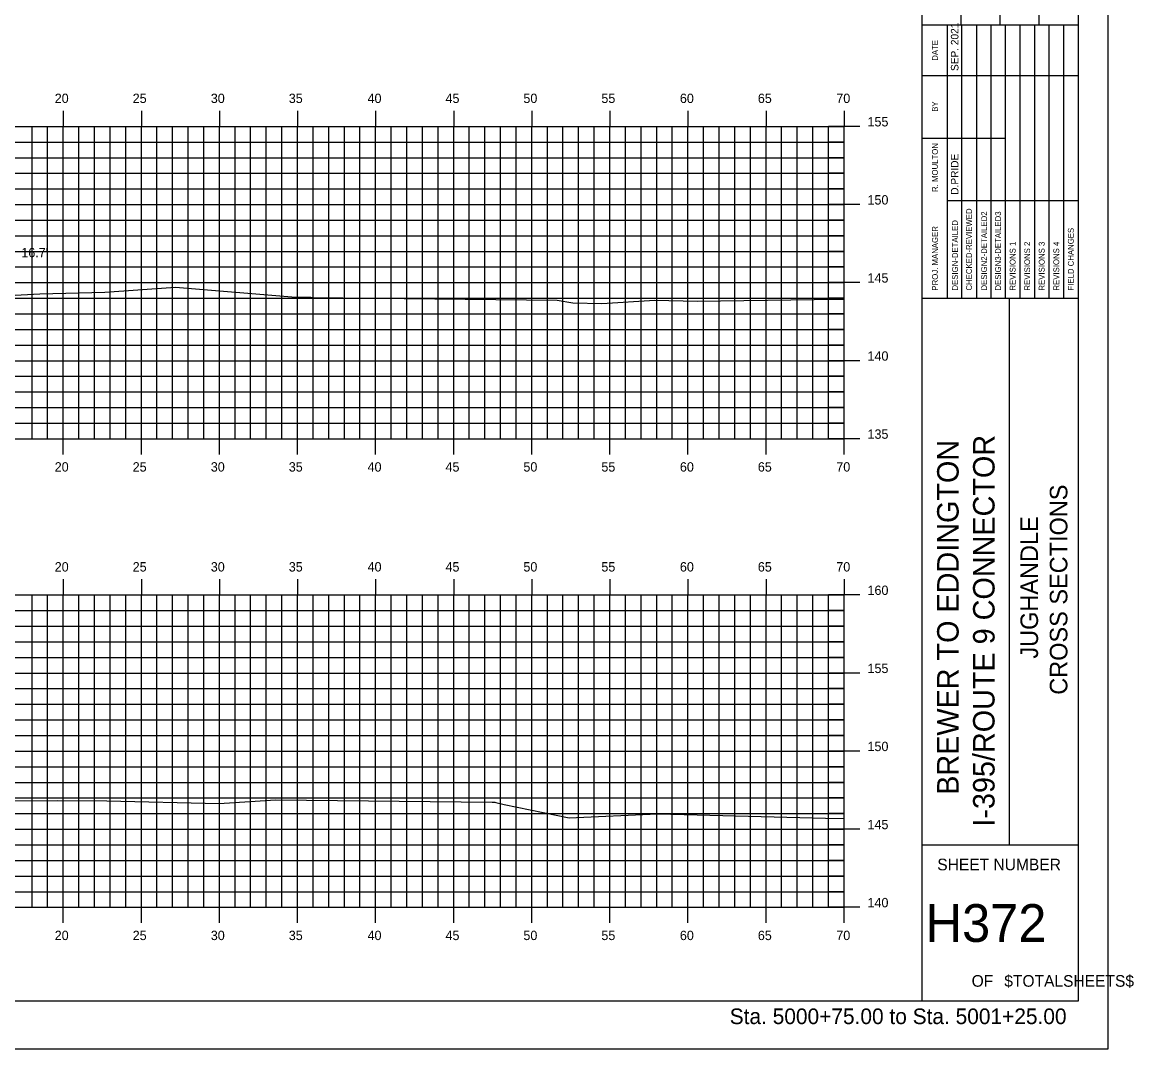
# Model space of a CAD drawing. Extents: x 850973 to 851145, y 365876 to 365986.
# Drawn here: x 851073.8 to 851144.9, y 365875.8 to 365941.5 of the extents above; entities that cross this region are included whole.
import ezdxf

# ---------------------------------------------------------------- set-up
doc = ezdxf.new("R2010")
doc.units = 0
for name, color, linetype in [('BORDER', 7, 'Continuous'), ('D_Text_Standard', 7, 'Continuous'), ('H_V ANNOTATION', 7, 'Continuous'), ('MAJOR', 7, 'Continuous'), ('MINOR', 7, 'Continuous'), ('PLOT BOUNDARY', 7, 'Continuous'), ('S_Roadway_Centerline', 7, 'Continuous')]:
    doc.layers.add(name, color=color, linetype=linetype)

msp = doc.modelspace()

# ---------------------------------------------------------------- linework, layer by layer
at = {"layer": 'BORDER'}
for p, q in [((851131.386, 365878.833), (851131.386, 365983.833)), ((851133.886, 365941.336), (851133.886, 365949.984)), ((851136.386, 365941.336), (851136.386, 365949.984)), ((851138.886, 365941.336), (851138.886, 365949.984)), ((851131.386, 365941.336), (851141.386, 365941.336)), ((851131.386, 365923.836), (851141.386, 365923.836)), ((851136.977, 365888.836), (851136.977, 365923.836)), ((851131.386, 365888.836), (851141.386, 365888.836))]:
    msp.add_line(p, q, dxfattribs=at)
msp.add_lwpolyline([(850981.386, 365878.833), (851141.386, 365878.833), (851141.386, 365983.833), (850981.386, 365983.833)], close=True, dxfattribs=at)
for points in [[(851133, 365938.086), (851133, 365941.336)], [(851133.933, 365923.839), (851133.933, 365941.336)], [(851134.865, 365941.336), (851134.865, 365923.839)], [(851135.796, 365923.839), (851135.796, 365941.336)], [(851136.728, 365923.839), (851136.728, 365941.336)], [(851137.66, 365923.839), (851137.66, 365941.336)], [(851138.591, 365923.839), (851138.591, 365941.336)], [(851139.523, 365923.839), (851139.523, 365941.336)], [(851140.455, 365923.839), (851140.455, 365941.336)], [(851133.001, 365923.839), (851133.001, 365940.63)], [(851131.386, 365938.086), (851141.386, 365938.086)], [(851131.386, 365934.086), (851133.001, 365934.086)], [(851133, 365934.086), (851136.727, 365934.086)], [(851133, 365930.086), (851141.386, 365930.086)]]:
    msp.add_lwpolyline(points, dxfattribs=at)
at = {"layer": 'MAJOR'}
for p, q in [((851076.385, 365935.835), (851076.385, 365934.833)), ((851081.385, 365935.835), (851081.385, 365934.833)), ((851086.385, 365935.835), (851086.385, 365934.833)), ((851091.385, 365935.835), (851091.385, 365934.833)), ((851096.385, 365935.835), (851096.385, 365934.833)), ((851101.385, 365935.835), (851101.385, 365934.833)), ((851106.385, 365935.835), (851106.385, 365934.833)), ((851111.385, 365935.835), (851111.385, 365934.833)), ((851116.385, 365935.835), (851116.385, 365934.833)), ((851121.385, 365935.835), (851121.385, 365934.833)), ((851126.385, 365935.835), (851126.385, 365934.833)), ((850986.385, 365934.833), (851126.385, 365934.833)), ((850986.385, 365934.833), (851126.385, 365934.833)), ((851076.385, 365914.833), (851076.385, 365934.833)), ((851081.385, 365914.833), (851081.385, 365934.833)), ((851086.385, 365914.833), (851086.385, 365934.833)), ((851091.385, 365914.833), (851091.385, 365934.833)), ((851096.385, 365914.833), (851096.385, 365934.833)), ((851101.385, 365914.833), (851101.385, 365934.833)), ((851106.385, 365914.833), (851106.385, 365934.833)), ((851111.385, 365914.833), (851111.385, 365934.833)), ((851116.385, 365914.833), (851116.385, 365934.833)), ((851121.385, 365914.833), (851121.385, 365934.833)), ((851127.387, 365934.833), (851125.383, 365934.833)), ((851126.385, 365914.833), (851126.385, 365934.833)), ((851126.385, 365914.833), (851126.385, 365934.833)), ((850986.385, 365929.833), (851126.385, 365929.833)), ((851127.387, 365929.833), (851125.383, 365929.833)), ((850986.385, 365924.833), (851126.385, 365924.833)), ((851127.387, 365924.833), (851125.383, 365924.833)), ((850986.385, 365919.833), (851126.385, 365919.833)), ((851127.387, 365919.833), (851125.383, 365919.833)), ((850986.385, 365914.833), (851126.385, 365914.833)), ((850986.385, 365914.833), (851126.385, 365914.833)), ((851076.385, 365913.831), (851076.385, 365914.833)), ((851081.385, 365913.831), (851081.385, 365914.833)), ((851086.385, 365913.831), (851086.385, 365914.833)), ((851091.385, 365913.831), (851091.385, 365914.833)), ((851096.385, 365913.831), (851096.385, 365914.833)), ((851101.385, 365913.831), (851101.385, 365914.833)), ((851106.385, 365913.831), (851106.385, 365914.833)), ((851111.385, 365913.831), (851111.385, 365914.833)), ((851116.385, 365913.831), (851116.385, 365914.833)), ((851121.385, 365913.831), (851121.385, 365914.833)), ((851127.387, 365914.833), (851125.383, 365914.833)), ((851126.385, 365913.831), (851126.385, 365914.833)), ((851076.385, 365905.835), (851076.385, 365904.833)), ((851081.385, 365905.835), (851081.385, 365904.833)), ((851086.385, 365905.835), (851086.385, 365904.833)), ((851091.385, 365905.835), (851091.385, 365904.833)), ((851096.385, 365905.835), (851096.385, 365904.833)), ((851101.385, 365905.835), (851101.385, 365904.833)), ((851106.385, 365905.835), (851106.385, 365904.833)), ((851111.385, 365905.835), (851111.385, 365904.833)), ((851116.385, 365905.835), (851116.385, 365904.833)), ((851121.385, 365905.835), (851121.385, 365904.833)), ((851126.385, 365905.835), (851126.385, 365904.833)), ((850986.385, 365904.833), (851126.385, 365904.833)), ((850986.385, 365904.833), (851126.385, 365904.833)), ((851076.385, 365884.833), (851076.385, 365904.833)), ((851081.385, 365884.833), (851081.385, 365904.833)), ((851086.385, 365884.833), (851086.385, 365904.833)), ((851091.385, 365884.833), (851091.385, 365904.833)), ((851096.385, 365884.833), (851096.385, 365904.833)), ((851101.385, 365884.833), (851101.385, 365904.833)), ((851106.385, 365884.833), (851106.385, 365904.833)), ((851111.385, 365884.833), (851111.385, 365904.833)), ((851116.385, 365884.833), (851116.385, 365904.833)), ((851121.385, 365884.833), (851121.385, 365904.833)), ((851127.387, 365904.833), (851125.383, 365904.833)), ((851126.385, 365884.833), (851126.385, 365904.833)), ((851126.385, 365884.833), (851126.385, 365904.833)), ((850986.385, 365899.833), (851126.385, 365899.833)), ((851127.387, 365899.833), (851125.383, 365899.833)), ((850986.385, 365894.833), (851126.385, 365894.833)), ((851127.387, 365894.833), (851125.383, 365894.833)), ((850986.385, 365889.833), (851126.385, 365889.833)), ((851127.387, 365889.833), (851125.383, 365889.833)), ((850986.385, 365884.833), (851126.385, 365884.833)), ((850986.385, 365884.833), (851126.385, 365884.833)), ((851076.385, 365883.831), (851076.385, 365884.833)), ((851081.385, 365883.831), (851081.385, 365884.833)), ((851086.385, 365883.831), (851086.385, 365884.833)), ((851091.385, 365883.831), (851091.385, 365884.833)), ((851096.385, 365883.831), (851096.385, 365884.833)), ((851101.385, 365883.831), (851101.385, 365884.833)), ((851106.385, 365883.831), (851106.385, 365884.833)), ((851111.385, 365883.831), (851111.385, 365884.833)), ((851116.385, 365883.831), (851116.385, 365884.833)), ((851121.385, 365883.831), (851121.385, 365884.833)), ((851127.387, 365884.833), (851125.383, 365884.833)), ((851126.385, 365883.831), (851126.385, 365884.833))]:
    msp.add_line(p, q, dxfattribs=at)
at = {"layer": 'MINOR'}
for p, q in [((851074.385, 365914.833), (851074.385, 365934.833)), ((851075.385, 365914.833), (851075.385, 365934.833)), ((851077.385, 365914.833), (851077.385, 365934.833)), ((851078.385, 365914.833), (851078.385, 365934.833)), ((851079.385, 365914.833), (851079.385, 365934.833)), ((851080.385, 365914.833), (851080.385, 365934.833)), ((851082.385, 365914.833), (851082.385, 365934.833)), ((851083.385, 365914.833), (851083.385, 365934.833)), ((851084.385, 365914.833), (851084.385, 365934.833)), ((851085.385, 365914.833), (851085.385, 365934.833)), ((851087.385, 365914.833), (851087.385, 365934.833)), ((851088.385, 365914.833), (851088.385, 365934.833)), ((851089.385, 365914.833), (851089.385, 365934.833)), ((851090.385, 365914.833), (851090.385, 365934.833)), ((851092.385, 365914.833), (851092.385, 365934.833)), ((851093.385, 365914.833), (851093.385, 365934.833)), ((851094.385, 365914.833), (851094.385, 365934.833)), ((851095.385, 365914.833), (851095.385, 365934.833)), ((851097.385, 365914.833), (851097.385, 365934.833)), ((851098.385, 365914.833), (851098.385, 365934.833)), ((851099.385, 365914.833), (851099.385, 365934.833)), ((851100.385, 365914.833), (851100.385, 365934.833)), ((851102.385, 365914.833), (851102.385, 365934.833)), ((851103.385, 365914.833), (851103.385, 365934.833)), ((851104.385, 365914.833), (851104.385, 365934.833)), ((851105.385, 365914.833), (851105.385, 365934.833)), ((851107.385, 365914.833), (851107.385, 365934.833)), ((851108.385, 365914.833), (851108.385, 365934.833)), ((851109.385, 365914.833), (851109.385, 365934.833)), ((851110.385, 365914.833), (851110.385, 365934.833)), ((851112.385, 365914.833), (851112.385, 365934.833)), ((851113.385, 365914.833), (851113.385, 365934.833)), ((851114.385, 365914.833), (851114.385, 365934.833)), ((851115.385, 365914.833), (851115.385, 365934.833)), ((851117.385, 365914.833), (851117.385, 365934.833)), ((851118.385, 365914.833), (851118.385, 365934.833)), ((851119.385, 365914.833), (851119.385, 365934.833)), ((851120.385, 365914.833), (851120.385, 365934.833)), ((851122.385, 365914.833), (851122.385, 365934.833)), ((851123.385, 365914.833), (851123.385, 365934.833)), ((851124.385, 365914.833), (851124.385, 365934.833)), ((851125.385, 365914.833), (851125.385, 365934.833)), ((850986.385, 365933.833), (851126.385, 365933.833)), ((851126.385, 365933.833), (851125.383, 365933.833)), ((850986.385, 365932.833), (851126.385, 365932.833)), ((851126.385, 365932.833), (851125.383, 365932.833)), ((850986.385, 365931.833), (851126.385, 365931.833)), ((851126.385, 365931.833), (851125.383, 365931.833)), ((850986.385, 365930.833), (851126.385, 365930.833)), ((851126.385, 365930.833), (851125.383, 365930.833)), ((850986.385, 365928.833), (851126.385, 365928.833)), ((851126.385, 365928.833), (851125.383, 365928.833)), ((850986.385, 365927.833), (851126.385, 365927.833)), ((851126.385, 365927.833), (851125.383, 365927.833)), ((850986.385, 365926.833), (851126.385, 365926.833)), ((851126.385, 365926.833), (851125.383, 365926.833)), ((850986.385, 365925.833), (851126.385, 365925.833)), ((851126.385, 365925.833), (851125.383, 365925.833)), ((850986.385, 365923.833), (851126.385, 365923.833)), ((851126.385, 365923.833), (851125.383, 365923.833)), ((850986.385, 365922.833), (851126.385, 365922.833)), ((851126.385, 365922.833), (851125.383, 365922.833)), ((850986.385, 365921.833), (851126.385, 365921.833)), ((851126.385, 365921.833), (851125.383, 365921.833)), ((850986.385, 365920.833), (851126.385, 365920.833)), ((851126.385, 365920.833), (851125.383, 365920.833)), ((850986.385, 365918.833), (851126.385, 365918.833)), ((851126.385, 365918.833), (851125.383, 365918.833)), ((850986.385, 365917.833), (851126.385, 365917.833)), ((851126.385, 365917.833), (851125.383, 365917.833)), ((850986.385, 365916.833), (851126.385, 365916.833)), ((851126.385, 365916.833), (851125.383, 365916.833)), ((850986.385, 365915.833), (851126.385, 365915.833)), ((851126.385, 365915.833), (851125.383, 365915.833)), ((851074.385, 365884.833), (851074.385, 365904.833)), ((851075.385, 365884.833), (851075.385, 365904.833)), ((851077.385, 365884.833), (851077.385, 365904.833)), ((851078.385, 365884.833), (851078.385, 365904.833)), ((851079.385, 365884.833), (851079.385, 365904.833)), ((851080.385, 365884.833), (851080.385, 365904.833)), ((851082.385, 365884.833), (851082.385, 365904.833)), ((851083.385, 365884.833), (851083.385, 365904.833)), ((851084.385, 365884.833), (851084.385, 365904.833)), ((851085.385, 365884.833), (851085.385, 365904.833)), ((851087.385, 365884.833), (851087.385, 365904.833)), ((851088.385, 365884.833), (851088.385, 365904.833)), ((851089.385, 365884.833), (851089.385, 365904.833)), ((851090.385, 365884.833), (851090.385, 365904.833)), ((851092.385, 365884.833), (851092.385, 365904.833)), ((851093.385, 365884.833), (851093.385, 365904.833)), ((851094.385, 365884.833), (851094.385, 365904.833)), ((851095.385, 365884.833), (851095.385, 365904.833)), ((851097.385, 365884.833), (851097.385, 365904.833)), ((851098.385, 365884.833), (851098.385, 365904.833)), ((851099.385, 365884.833), (851099.385, 365904.833)), ((851100.385, 365884.833), (851100.385, 365904.833)), ((851102.385, 365884.833), (851102.385, 365904.833)), ((851103.385, 365884.833), (851103.385, 365904.833)), ((851104.385, 365884.833), (851104.385, 365904.833)), ((851105.385, 365884.833), (851105.385, 365904.833)), ((851107.385, 365884.833), (851107.385, 365904.833)), ((851108.385, 365884.833), (851108.385, 365904.833)), ((851109.385, 365884.833), (851109.385, 365904.833)), ((851110.385, 365884.833), (851110.385, 365904.833)), ((851112.385, 365884.833), (851112.385, 365904.833)), ((851113.385, 365884.833), (851113.385, 365904.833)), ((851114.385, 365884.833), (851114.385, 365904.833)), ((851115.385, 365884.833), (851115.385, 365904.833)), ((851117.385, 365884.833), (851117.385, 365904.833)), ((851118.385, 365884.833), (851118.385, 365904.833)), ((851119.385, 365884.833), (851119.385, 365904.833)), ((851120.385, 365884.833), (851120.385, 365904.833)), ((851122.385, 365884.833), (851122.385, 365904.833)), ((851123.385, 365884.833), (851123.385, 365904.833)), ((851124.385, 365884.833), (851124.385, 365904.833)), ((851125.385, 365884.833), (851125.385, 365904.833)), ((850986.385, 365903.833), (851126.385, 365903.833)), ((851126.385, 365903.833), (851125.383, 365903.833)), ((850986.385, 365902.833), (851126.385, 365902.833)), ((851126.385, 365902.833), (851125.383, 365902.833)), ((850986.385, 365901.833), (851126.385, 365901.833)), ((851126.385, 365901.833), (851125.383, 365901.833)), ((850986.385, 365900.833), (851126.385, 365900.833)), ((851126.385, 365900.833), (851125.383, 365900.833)), ((850986.385, 365898.833), (851126.385, 365898.833)), ((851126.385, 365898.833), (851125.383, 365898.833)), ((850986.385, 365897.833), (851126.385, 365897.833)), ((851126.385, 365897.833), (851125.383, 365897.833)), ((850986.385, 365896.833), (851126.385, 365896.833)), ((851126.385, 365896.833), (851125.383, 365896.833)), ((850986.385, 365895.833), (851126.385, 365895.833)), ((851126.385, 365895.833), (851125.383, 365895.833)), ((850986.385, 365893.833), (851126.385, 365893.833)), ((851126.385, 365893.833), (851125.383, 365893.833)), ((850986.385, 365892.833), (851126.385, 365892.833)), ((851126.385, 365892.833), (851125.383, 365892.833)), ((850986.385, 365891.833), (851126.385, 365891.833)), ((851126.385, 365891.833), (851125.383, 365891.833)), ((850986.385, 365890.833), (851126.385, 365890.833)), ((851126.385, 365890.833), (851125.383, 365890.833)), ((850986.385, 365888.833), (851126.385, 365888.833)), ((851126.385, 365888.833), (851125.383, 365888.833)), ((850986.385, 365887.833), (851126.385, 365887.833)), ((851126.385, 365887.833), (851125.383, 365887.833)), ((850986.385, 365886.833), (851126.385, 365886.833)), ((851126.385, 365886.833), (851125.383, 365886.833)), ((850986.385, 365885.833), (851126.385, 365885.833)), ((851126.385, 365885.833), (851125.383, 365885.833))]:
    msp.add_line(p, q, dxfattribs=at)
at = {"layer": 'PLOT BOUNDARY'}
msp.add_lwpolyline([(850973.292, 365875.774), (851143.292, 365875.774), (851143.292, 365985.774), (850973.292, 365985.774)], close=True, dxfattribs=at)
at = {"layer": 'S_Roadway_Centerline'}
for points in [[(851071.299, 365923.923), (851074.89, 365924.107), (851079.05, 365924.221), (851083.568, 365924.545), (851091.022, 365923.932), (851092.243, 365923.891), (851092.314, 365923.871), (851108.019, 365923.7), (851109.01, 365923.549), (851110.868, 365923.49), (851114.266, 365923.703), (851116.987, 365923.648), (851124.466, 365923.756), (851126.385, 365923.764)], [(851068.958, 365891.637), (851076.022, 365891.665), (851079.185, 365891.648), (851086.363, 365891.49), (851089.981, 365891.708), (851103.849, 365891.573), (851104.023, 365891.562), (851104.076, 365891.544), (851104.628, 365891.414), (851108.776, 365890.558), (851114.441, 365890.825), (851116.14, 365890.77), (851125.195, 365890.536), (851126.385, 365890.512)]]:
    msp.add_lwpolyline(points, dxfattribs=at)

# ---------------------------------------------------------------- texts
at = {"layer": 'BORDER'}
for s, height, p in [('SEP. 2021', 0.4845, (851133.708, 365938.382)), ('DATE', 0.3714, (851132.39, 365939.042)), ('BY', 0.3714, (851132.39, 365935.771)), ('R. MOULTON', 0.3727, (851132.39, 365930.639)), ('D.PRIDE', 0.4845, (851133.708, 365930.459)), ('CHECKED-REVIEWED', 0.37275, (851134.567, 365924.324)), ('DESIGN2-DETAILED2', 0.37275, (851135.535, 365924.324)), ('DESIGN3-DETAILED3', 0.37275, (851136.43, 365924.324)), ('DESIGN-DETAILED', 0.37275, (851133.672, 365924.324)), ('PROJ. MANAGER', 0.37275, (851132.39, 365924.324)), ('FIELD CHANGES', 0.37275, (851141.088, 365924.324)), ('REVISIONS 1', 0.37275, (851137.362, 365924.324)), ('REVISIONS 2', 0.37275, (851138.293, 365924.324)), ('REVISIONS 3', 0.37275, (851139.225, 365924.324)), ('REVISIONS 4', 0.37275, (851140.157, 365924.324)), ('BREWER TO EDDINGTON', 1.37787, (851133.719, 365892.038)), ('I-395/ROUTE 9 CONNECTOR', 1.37787, (851136.02, 365889.998)), ('CROSS SECTIONS', 1.125, (851140.683, 365898.444)), ('JUGHANDLE', 1.125, (851138.804, 365900.756))]:
    msp.add_text(s, height=height, rotation=90, dxfattribs=at).set_placement(p)
for s, height, p in [('SHEET NUMBER', 0.74527, (851132.351, 365887.2)), ('H372', 2.4194, (851131.605, 365882.616)), ('OF', 0.7453, (851134.552, 365879.746)), ('$TOTALSHEETS$', 0.74527, (851136.642, 365879.746))]:
    msp.add_text(s, height=height, dxfattribs=at).set_placement(p)
at = {"layer": 'D_Text_Standard'}
msp.add_text("16.7'", height=0.6, dxfattribs=at).set_placement((851073.701, 365926.455))
at = {"layer": 'H_V ANNOTATION'}
for s, height, p in [('20', 0.6, (851075.839, 365936.333)), ('25', 0.6, (851080.831, 365936.333)), ('30', 0.6, (851085.834, 365936.333)), ('35', 0.6, (851090.826, 365936.333)), ('40', 0.6, (851095.871, 365936.333)), ('45', 0.6, (851100.863, 365936.333)), ('50', 0.6, (851105.85, 365936.333)), ('55', 0.6, (851110.842, 365936.333)), ('60', 0.6, (851115.871, 365936.333)), ('65', 0.6, (851120.863, 365936.333)), ('70', 0.6, (851125.887, 365936.333)), ('155', 0.6, (851127.885, 365934.833)), ('150', 0.6, (851127.885, 365929.833)), ('145', 0.6, (851127.885, 365924.833)), ('140', 0.6, (851127.885, 365919.833)), ('135', 0.6, (851127.885, 365914.833)), ('20', 0.6, (851075.839, 365912.733)), ('25', 0.6, (851080.831, 365912.733)), ('30', 0.6, (851085.834, 365912.733)), ('35', 0.6, (851090.826, 365912.733)), ('40', 0.6, (851095.871, 365912.733)), ('45', 0.6, (851100.863, 365912.733)), ('50', 0.6, (851105.85, 365912.733)), ('55', 0.6, (851110.842, 365912.733)), ('60', 0.6, (851115.871, 365912.733)), ('65', 0.6, (851120.863, 365912.733)), ('70', 0.6, (851125.887, 365912.733)), ('20', 0.6, (851075.839, 365906.333)), ('25', 0.6, (851080.831, 365906.333)), ('30', 0.6, (851085.834, 365906.333)), ('35', 0.6, (851090.826, 365906.333)), ('40', 0.6, (851095.871, 365906.333)), ('45', 0.6, (851100.863, 365906.333)), ('50', 0.6, (851105.85, 365906.333)), ('55', 0.6, (851110.842, 365906.333)), ('60', 0.6, (851115.871, 365906.333)), ('65', 0.6, (851120.863, 365906.333)), ('70', 0.6, (851125.887, 365906.333)), ('160', 0.6, (851127.885, 365904.833)), ('155', 0.6, (851127.885, 365899.833)), ('150', 0.6, (851127.885, 365894.833)), ('145', 0.6, (851127.885, 365889.833)), ('140', 0.6, (851127.885, 365884.833)), ('20', 0.6, (851075.839, 365882.733)), ('25', 0.6, (851080.831, 365882.733)), ('30', 0.6, (851085.834, 365882.733)), ('35', 0.6, (851090.826, 365882.733)), ('40', 0.6, (851095.871, 365882.733)), ('45', 0.6, (851100.863, 365882.733)), ('50', 0.6, (851105.85, 365882.733)), ('55', 0.6, (851110.842, 365882.733)), ('60', 0.6, (851115.871, 365882.733)), ('65', 0.6, (851120.863, 365882.733)), ('70', 0.6, (851125.887, 365882.733)), ('Sta. 5000+75.00 to Sta. 5001+25.00', 1.0002, (851119.062, 365877.353))]:
    msp.add_text(s, height=height, dxfattribs=at).set_placement(p)

doc.saveas('drawing.dxf')
